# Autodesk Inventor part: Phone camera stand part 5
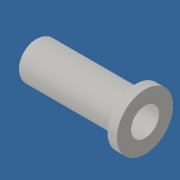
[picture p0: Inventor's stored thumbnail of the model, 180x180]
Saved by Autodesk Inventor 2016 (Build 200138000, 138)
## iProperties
Created: 2016-02
Part Number: Phone camera stand part 5
Material: Generic
Document SubType Name: Modeling
Designer: Miha
Density: 1 g/cm^3
Appearance: Default
Author: Miha
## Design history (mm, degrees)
sketch "Sketch1"
  geometry: C1 r 4 at (0, 0); 1 further point
  constraints: 1 centre point, 1 coincident
  dimensions: "d0" = 8 diameter of C1
extrude "Extrusion1" new body sketch "Sketch1" distance "d1" = 21.5; taper "d2" = 0 deg
sketch "Sketch2"
  geometry: C1 r 6 at (0, 0); 1 further point
  constraints: 1 centre point, 1 coincident
  dimensions: "d3" = 12 diameter of C1
extrude "Extrusion2" join sketch "Sketch2" distance "d4" = 2; taper "d5" = 0 deg
sketch "Sketch3"
  geometry: C1 r 1.7 at (0, 0); 1 further point
  constraints: 1 centre point, 1 coincident
  dimensions: "d6" = 3.4 diameter of C1
extrude "Extrusion3" cut sketch "Sketch3" stored distance "d7" = 2; taper "d8" = 0 deg
sketch "Sketch4"
  geometry: C1 r 3 at (0, 0); 1 further point
  constraints: 1 centre point, 1 coincident
  dimensions: "d9" = 6 diameter of C1
extrude "Extrusion4" cut sketch "Sketch4" distance "d10" = 12; taper "d11" = 0 deg
fillet "Fillet1" dims "d12" = 1
fillet "Fillet3" dims "d14" = 1.3
body "Solid1"
